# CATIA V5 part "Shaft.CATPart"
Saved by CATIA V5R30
Part number: Part2
Material "Iron": density 7870 kg/m3, Young's modulus 2.11e+11 Pa, Poisson ratio 0.291, thermal expansion 1.21e-05 1/K
Bounding box of the stored display mesh (mm): x -20.121 to 20.121, y 0 to 300, z -20.121 to 20.121
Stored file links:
  D:\PROJECTS\CATIA V56R 2020\Resources\Tutorial Files\c19_catia_v5_6r2019_tut\C19_tut_02.CATPart\Shaft.CATPart
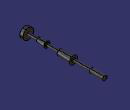
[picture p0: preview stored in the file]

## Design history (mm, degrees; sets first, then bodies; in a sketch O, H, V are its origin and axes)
Body1 (main body), material "Iron"
  Sketch1 on yz-plane, origin (0, 0, 0), H (0, 1, 0), V (0, 0, 1)
    line L1 (0, 0) -> (0, 20.127)
    line L2 (0, 20.127) -> (12.0221, 20.127)
    line L3 (12.0221, 20.127) -> (12.0221, 5.2746)
    point P3 (12.0221, 5.2746)
    line L4 (12.0221, 5.2746) -> (51.1457, 5.2746)
    line L5 (51.1457, 5.2746) -> (51.1457, 8.5349)
    line L6 (51.1457, 8.5349) -> (82.0221, 11.1079)
    line L7 (82.0221, 11.1079) -> (82.0221, 5.2746)
    point P7 (82.0221, 5.2746)
    line L8 (82.0221, 5.2746) -> (132.0221, 5.2746)
    line L9 (132.0221, 5.2746) -> (132.0221, 10.9839)
    line L10 (132.0221, 10.9839) -> (182.0221, 15.1506)
    line L11 (182.0221, 15.1506) -> (182.0221, 5.2746)
    point P11 (182.0221, 5.2746)
    line L12 (182.0221, 5.2746) -> (250, 5.2746)
    line L13 (250, 5.2746) -> (250, 8.5349)
    line L14 (250, 8.5349) -> (300, 8.5349)
    line L15 (300, 8.5349) -> (300, 0)
    point P15 (300, 0)
    axis line L16 (0, 0) -> (300, 0)
    distance L15 L1 = 300
    distance L13 L1 = 250
    distance L11 L7 = 100
    distance L3 L7 = 70
    distance L9 L11 = 50
    vertical: L1 V, L3 V, L5 V, L7 V, L9 V, L11 V, L13 V, L15 V
    horizontal: L2 H, L4 H, L8 H, L12 H, L14 H, L16 H
    coincidence: L6 P3, P7 L4, P11 L4, P15 H
    parallelism: L10 L6
  Shaft1: profile Sketch1, axis Sketch1.L16, angle 360
  Fillet1: radius 2, on edge [face of Shaft1 from Sketch1.L7 | face of Shaft1 from Sketch1.L8]; edge [face of Shaft1 from Sketch1.L4 | face of Shaft1 from Sketch1.L5]; edge [face of Shaft1 from Sketch1.L8 | face of Shaft1 from Sketch1.L9]; edge [face of Shaft1 from Sketch1.L11 | face of Shaft1 from Sketch1.L12]; edge [face of Shaft1 from Sketch1.L12 | face of Shaft1 from Sketch1.L13]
